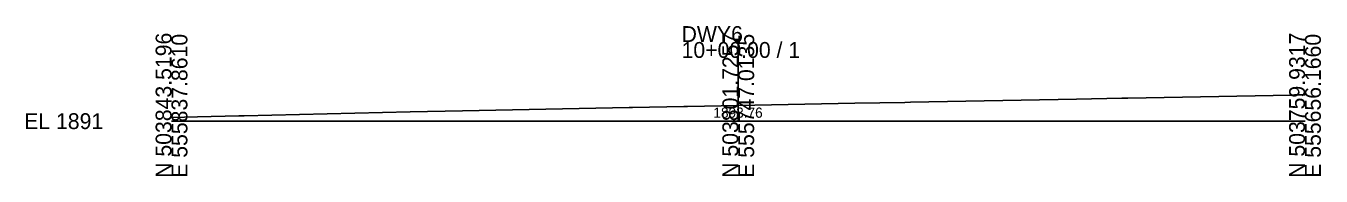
# Model space of a CAD drawing. Extents: x -26 to 1503, y -10 to 1030.
# Drawn here: x -25.7 to 202.8, y -9.7 to 16.8 of the extents above; entities that cross this region are included whole.
import ezdxf

# ---------------------------------------------------------------- set-up
doc = ezdxf.new("R2010")
doc.units = 0
for name, color, linetype in [('Default', 7, 'Continuous'), ('Exist Cross Section Cell', 7, 'Continuous'), ('Exist XS Center Line Elevation Label', 7, 'Continuous'), ('Exist XS Ground Line', 7, 'Continuous')]:
    doc.layers.add(name, color=color, linetype=linetype)

msp = doc.modelspace()

# ---------------------------------------------------------------- linework, layer by layer
at = {"layer": 'Exist Cross Section Cell'}
for p, q in [((100, 0), (100, 13.96)), ((0, 0), (100, 0)), ((100, 0), (200, 0))]:
    msp.add_line(p, q, dxfattribs=at)
at = {"layer": 'Exist XS Ground Line'}
for p, q in [((168.72, 4.07), (197.59, 4.61)), ((197.59, 4.61), (198.12, 4.62)), ((198.12, 4.62), (200, 4.65)), ((51.36, 1.82), (80.77, 2.41)), ((80.77, 2.41), (81.34, 2.42)), ((81.34, 2.42), (90.38, 2.59)), ((90.38, 2.59), (91.04, 2.6)), ((91.04, 2.6), (100, 2.76)), ((100, 2.76), (120.56, 3.15)), ((120.56, 3.15), (129.4, 3.31)), ((129.4, 3.31), (130.37, 3.34)), ((130.37, 3.34), (159.71, 3.9)), ((159.71, 3.9), (167.69, 4.05)), ((167.69, 4.05), (168.72, 4.07)), ((0, 0.66), (4.61, 0.74)), ((4.61, 0.74), (11.86, 0.91)), ((11.86, 0.91), (12.79, 0.94)), ((12.79, 0.94), (42.09, 1.64)), ((42.09, 1.64), (51.36, 1.82))]:
    msp.add_line(p, q, dxfattribs=at)

# ---------------------------------------------------------------- texts
at = {"layer": 'Default'}
msp.add_text('-', height=0.0001, dxfattribs=at).set_placement((0, 0))
at = {"layer": 'Exist Cross Section Cell'}
for s, p in [('DWY6', (90, 13.96)), ('10+00.00 / 1', (90, 11.16)), ('EL 1891', (-26, -1.4))]:
    msp.add_text(s, height=2.8, dxfattribs=at).set_placement(p)
for s, p in [('N 503843.5196', (0, -10)), ('E 555837.8610', (2.8, -10)), ('N 503801.7257', (100, -10)), ('E 555747.0135', (102.8, -10)), ('N 503759.9317', (200, -10)), ('E 555656.1660', (202.8, -10))]:
    msp.add_text(s, height=2.8, rotation=90, dxfattribs=at).set_placement(p)
at = {"layer": 'Exist XS Center Line Elevation Label'}
msp.add_text('1893.76', height=1.8, dxfattribs=at).set_placement((95.61, 0.6))

doc.saveas('drawing.dxf')
